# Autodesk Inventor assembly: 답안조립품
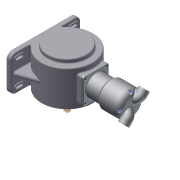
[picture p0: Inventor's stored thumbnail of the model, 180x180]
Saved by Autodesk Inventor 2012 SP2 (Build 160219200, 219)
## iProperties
Created: 2015-06
Part Number: 답안조립품
Document SubType Name: Assembly
Designer: Administrator
Author: Administrator
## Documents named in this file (15)
- C:\Users\Administrator\Desktop\450605V1026\답안조립품.iam
- C:\Users\Administrator\Desktop\450605V1026\본체.ipt
- C:\Users\Administrator\Desktop\450605V1026\실린더.ipt
- C:\Users\Administrator\Desktop\450605V1026\실린더헤드.ipt
- C:\Users\Administrator\Desktop\450605V1026\메인커버.ipt
- C:\Users\Administrator\Desktop\450605V1026\메인 크랭크 축-구동부.ipt
- C:\Users\Administrator\Desktop\450605V1026\크랭크 서브축.ipt
- C:\Users\Administrator\Desktop\450605V1026\커넥팅 로드.ipt
- C:\Users\Administrator\Desktop\450605V1026\베어링 NA 4902.ipt
- C:\Users\Administrator\Desktop\450605V1026\베어링 6204.ipt
- C:\Users\Administrator\Desktop\450605V1026\피스톤.ipt
- C:\Users\Administrator\Desktop\450605V1026\피스톤 핀.ipt
- C:\Users\Administrator\Desktop\450605V1026\오일실.ipt
- C:\Users\Administrator\Desktop\450605V1026\M4x0.7.ipt
- C:\Users\Administrator\Desktop\450605V1026\M5x0.8.ipt
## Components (14 placed, 4 different names)
1. 피스톤:1
2. 피스톤 핀:1
3. M4x0.7:1
4. M4x0.7:2
5. M4x0.7:3
6. M4x0.7:4
7. M5x0.8:1
8. M5x0.8:2
9. M5x0.8:3
10. M5x0.8:4
11. M4x0.7:5
12. M4x0.7:6
13. M4x0.7:7
14. M4x0.7:8
